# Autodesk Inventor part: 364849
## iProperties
Company: Mayer & Müller AG Schaltgeräte
Created: 2005-12
Part Number: 364849
Material: 1.0718.07
Description: Kern
Document SubType Name: Modeling
Designer: I.Baliuc
Manufacturer: Standard
Standards Organization: Custom
Density: 7.84 g/cm^3
Mass: 439.749 g
Surface Area: 140.82 cm^2
Volume: 56.0904 cm^3
HalbzeugNorm: DIN 178
Zweck: für Blasspule / DC-Schalter
Abmessung: 40x40-41
dX*dY*dZ: 41mm x 40mm x 40mm
Flaeche: 14082 mm²
Volumen: 56090 mm³
Author: T.Messerschmitt
Keywords: 380158
Revision Number: 364849
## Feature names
1. Extrusion2
2. Drehung1 [Revolution]
3. M10x1.5 / 15 mm tief x 21 mm tief_1 [Hole]
4. M10x1.5 / 15 mm tief x 21,00000000 mm tief_1 [Hole]
5. 5x M10x1.5 / 12 mm tief x 21,00000000 mm tief_1 [Hole]
6. Ø6,65 mm x 14 mm tief_1 [Hole]
7. Ø6,65 mm x 14 mm tief_2 [Hole]
